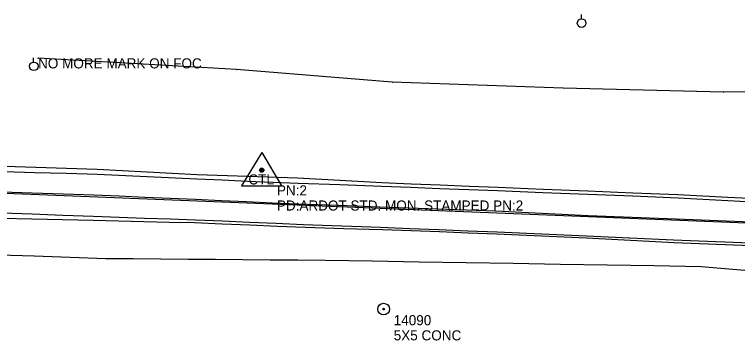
# Model space of a CAD drawing. Extents: x 1138803 to 1169983, y 1655906 to 1658226.
# Drawn here: x 1140860.2 to 1141217.9, y 1657591.3 to 1657752.7 of the extents above; entities that cross this region are included whole.
import ezdxf

# ---------------------------------------------------------------- set-up
doc = ezdxf.new("R2010")
doc.units = 0
for name, color, linetype in [('S_EDGE_PAVEMENT', 7, 'Continuous'), ('S_EXISTING_ALIGNMENT', 7, 'Continuous'), ('S_FIBER_OPTIC_CABLE', 7, 'Continuous'), ('S_FIBER_OPTIC_CABLE_ANNOT', 7, 'Continuous'), ('S_IRON_PIN', 7, 'Continuous'), ('S_IRON_PIN_ANNOT', 7, 'Continuous'), ('S_PAVEMENT_CROWN', 7, 'Continuous'), ('S_PRIMARY_CTL', 7, 'Continuous'), ('S_PRIMARY_CTL_ANNOT', 7, 'Continuous'), ('S_SHOULDER', 7, 'Continuous'), ('S_TREE', 7, 'Continuous'), ('S_UTILITY_POLE', 7, 'Continuous'), ('S_UTL_PT_SYM', 7, 'Continuous')]:
    doc.layers.add(name, color=color, linetype=linetype)

msp = doc.modelspace()

# ---------------------------------------------------------------- linework, layer by layer
at = {"layer": 'S_EDGE_PAVEMENT'}
for points in [[(1141237.68, 1657659.07), (1141213.11, 1657660.44), (1141188.53, 1657661.82), (1141166.16, 1657662.69), (1141143.79, 1657663.56), (1141121.5, 1657664.45), (1141099.22, 1657665.34), (1141084.84, 1657665.89), (1141070.46, 1657666.44), (1141056.08, 1657666.99), (1141041.7, 1657667.54), (1141021.13, 1657668.28), (1141000.56, 1657669.02), (1140988.03, 1657669.56), (1140975.5, 1657670.09), (1140962.97, 1657670.62), (1140950.44, 1657671.15), (1140925.82, 1657672.35), (1140901.19, 1657673.55), (1140885.75, 1657673.96), (1140870.32, 1657674.37), (1140854.89, 1657674.78)], [(1141224.13, 1657639.55), (1141211.47, 1657640.03), (1141198.81, 1657640.52), (1141186.15, 1657641.01), (1141164.68, 1657642.01), (1141143.21, 1657643), (1141121.06, 1657643.93), (1141098.92, 1657644.86), (1141084.52, 1657645.44), (1141070.12, 1657646.02), (1141055.72, 1657646.59), (1141041.32, 1657647.17), (1141022.14, 1657647.89), (1141002.95, 1657648.61), (1140989.66, 1657649.18), (1140976.38, 1657649.74), (1140963.09, 1657650.3), (1140949.8, 1657650.86), (1140937.19, 1657651.32), (1140924.57, 1657651.77), (1140911.95, 1657652.22), (1140899.33, 1657652.68), (1140884.12, 1657653.22), (1140868.91, 1657653.76), (1140853.71, 1657654.29)]]:
    msp.add_lwpolyline(points, dxfattribs=at)
at = {"layer": 'S_EXISTING_ALIGNMENT'}
msp.add_line((1140481.53, 1657679.14), (1142022.15, 1657617.46), dxfattribs=at)
at = {"layer": 'S_FIBER_OPTIC_CABLE'}
for p, q in [((1140970.08, 1657725.45), (1140871.86, 1657731)), ((1141047.12, 1657719.21), (1140970.08, 1657725.45)), ((1141131.62, 1657716.24), (1141047.12, 1657719.21)), ((1141210.99, 1657714.26), (1141131.62, 1657716.24)), ((1141275.94, 1657715.01), (1141210.99, 1657714.26))]:
    msp.add_line(p, q, dxfattribs=at)
at = {"layer": 'S_IRON_PIN'}
for radius in [2.91, 0.411, 0.262, 0.212, 0.145, 0.0822, 0.0581]:
    msp.add_circle((1141042.8, 1657606.84), radius, dxfattribs=at)
at = {"layer": 'S_PAVEMENT_CROWN'}
msp.add_lwpolyline([(1141237.14, 1657649.33), (1141212.32, 1657650.33), (1141187.51, 1657651.33), (1141165.74, 1657652.19), (1141143.98, 1657653.05), (1141121.1, 1657654.2), (1141098.22, 1657655.34), (1141083.85, 1657655.85), (1141069.47, 1657656.36), (1141055.1, 1657656.87), (1141040.72, 1657657.38), (1141020.5, 1657658.08), (1141000.27, 1657658.77), (1140987.64, 1657659.35), (1140975.02, 1657659.93), (1140962.39, 1657660.52), (1140949.76, 1657661.1), (1140937.19, 1657661.62), (1140924.62, 1657662.15), (1140912.05, 1657662.67), (1140899.48, 1657663.2), (1140884.24, 1657663.71), (1140869, 1657664.22), (1140853.76, 1657664.73)], dxfattribs=at)
at = {"layer": 'S_PRIMARY_CTL'}
for p, q in [((1140982.52, 1657684.32), (1140972.48, 1657667.8)), ((1140982.52, 1657684.32), (1140992.34, 1657667.8)), ((1140972.48, 1657667.8), (1140992.34, 1657667.8))]:
    msp.add_line(p, q, dxfattribs=at)
for radius in [1.04, 0.609, 0.344]:
    msp.add_circle((1140982.52, 1657675.62), radius, dxfattribs=at)
at = {"layer": 'S_SHOULDER'}
for points in [[(1141237.88, 1657660.9), (1141213.1, 1657662.14), (1141188.31, 1657663.38), (1141166.1, 1657664.31), (1141143.9, 1657665.25), (1141121.7, 1657666.11), (1141099.5, 1657666.98), (1141085.12, 1657667.55), (1141070.74, 1657668.13), (1141056.36, 1657668.7), (1141041.98, 1657669.28), (1141021.08, 1657670.47), (1141000.19, 1657671.66), (1140975.41, 1657672.45), (1140950.63, 1657673.24), (1140925.86, 1657674.62), (1140901.09, 1657676), (1140885.89, 1657676.49), (1140870.68, 1657676.98), (1140855.47, 1657677.47)], [(1141224.31, 1657638.17), (1141211.72, 1657638.64), (1141199.14, 1657639.1), (1141186.55, 1657639.57), (1141164.87, 1657640.77), (1141143.19, 1657641.97), (1141120.98, 1657642.98), (1141098.76, 1657643.99), (1141084.63, 1657644.5), (1141070.51, 1657645.01), (1141056.39, 1657645.51), (1141042.26, 1657646.02), (1141023.09, 1657646.64), (1141003.92, 1657647.25), (1140990.23, 1657647.81), (1140976.55, 1657648.37), (1140962.86, 1657648.92), (1140949.17, 1657649.48), (1140936.66, 1657649.79), (1140924.15, 1657650.11), (1140911.64, 1657650.43), (1140899.13, 1657650.74), (1140883.99, 1657651.08), (1140868.85, 1657651.41), (1140853.71, 1657651.75)]]:
    msp.add_lwpolyline(points, dxfattribs=at)
at = {"layer": 'S_TREE'}
msp.add_lwpolyline([(1140852.21, 1657633.74), (1140869.95, 1657633.15), (1140887.68, 1657632.56), (1140905.42, 1657631.97), (1140918.97, 1657631.86), (1140932.53, 1657631.74), (1140946.09, 1657631.63), (1140959.64, 1657631.52), (1140973.2, 1657631.4), (1140986.75, 1657631.29), (1141000.31, 1657631.17), (1141013.86, 1657631.06), (1141037.12, 1657630.67), (1141060.39, 1657630.29), (1141083.65, 1657629.9), (1141106.91, 1657629.51), (1141130.17, 1657629.13), (1141153.43, 1657628.74), (1141176.7, 1657628.36), (1141199.96, 1657627.97), (1141215.64, 1657626.62), (1141231.32, 1657625.27)], dxfattribs=at)
at = {"layer": 'S_UTILITY_POLE'}
for p, q in [((1141140.65, 1657750.61), (1141140.65, 1657752.71)), ((1140869.63, 1657729.18), (1140869.63, 1657731.29))]:
    msp.add_line(p, q, dxfattribs=at)
for centre in [(1141140.77, 1657748.46), (1140869.75, 1657727.04)]:
    msp.add_circle(centre, 2.13, dxfattribs=at)
at = {"layer": 'S_UTL_PT_SYM'}
for points in [[(1140871.86, 1657731), (1140871.86, 1657731.05), (1140871.86, 1657731), (1140871.81, 1657731), (1140871.86, 1657731), (1140871.86, 1657730.95), (1140871.86, 1657731), (1140871.91, 1657731)], [(1140970.08, 1657725.45), (1140970.08, 1657725.5), (1140970.08, 1657725.45), (1140970.03, 1657725.45), (1140970.08, 1657725.45), (1140970.08, 1657725.4), (1140970.08, 1657725.45), (1140970.13, 1657725.45)], [(1141047.12, 1657719.21), (1141047.12, 1657719.26), (1141047.12, 1657719.21), (1141047.07, 1657719.21), (1141047.12, 1657719.21), (1141047.12, 1657719.16), (1141047.12, 1657719.21), (1141047.17, 1657719.21)], [(1141131.62, 1657716.24), (1141131.62, 1657716.29), (1141131.62, 1657716.24), (1141131.57, 1657716.24), (1141131.62, 1657716.24), (1141131.62, 1657716.19), (1141131.62, 1657716.24), (1141131.67, 1657716.24)], [(1141210.99, 1657714.26), (1141210.99, 1657714.31), (1141210.99, 1657714.26), (1141210.94, 1657714.26), (1141210.99, 1657714.26), (1141210.99, 1657714.21), (1141210.99, 1657714.26), (1141211.04, 1657714.26)]]:
    msp.add_lwpolyline(points, dxfattribs=at)

# ---------------------------------------------------------------- texts
at = {"layer": 'S_FIBER_OPTIC_CABLE_ANNOT'}
msp.add_text('NO MORE MARK ON FOC', height=5, dxfattribs=at).set_placement((1140871.86, 1657726))
at = {"layer": 'S_IRON_PIN_ANNOT'}
for s, p in [('14090', (1141047.8, 1657598.84)), ('5X5 CONC', (1141047.8, 1657591.34))]:
    msp.add_text(s, height=5, dxfattribs=at).set_placement(p)
at = {"layer": 'S_PRIMARY_CTL'}
msp.add_text('CTL', height=5, rotation=360, dxfattribs=at).set_placement((1140975.93, 1657668.54))
at = {"layer": 'S_PRIMARY_CTL_ANNOT'}
for s, p in [('PN:2', (1140990.02, 1657663.12)), ('PD:ARDOT STD. MON. STAMPED PN:2', (1140990.02, 1657655.62))]:
    msp.add_text(s, height=5, dxfattribs=at).set_placement(p)

doc.saveas('drawing.dxf')
